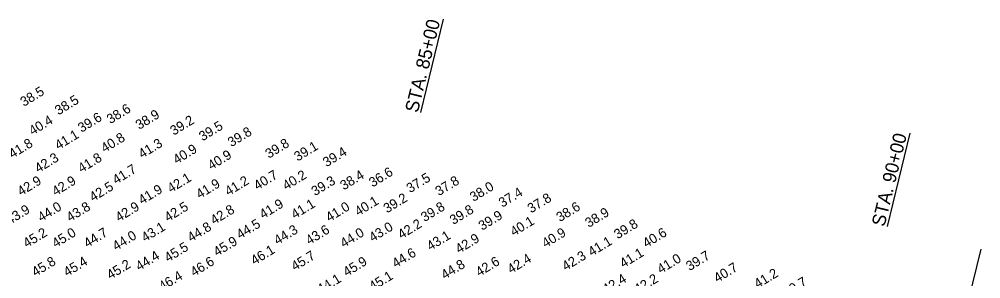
# Model space of a CAD drawing. Extents: x 409260 to 414340, y 1188556 to 1192902.
# Drawn here: x 412335 to 413336, y 1190993 to 1191263 of the extents above; entities that cross this region are included whole.
import ezdxf

# ---------------------------------------------------------------- set-up
doc = ezdxf.new("R2010")
doc.units = 0
for name, color, linetype in [('V-ALGN-TEXT', 7, 'Continuous'), ('V-ANNO-MATC', 7, 'Continuous'), ('V-TOPO-SOUN', 7, 'Continuous')]:
    doc.layers.add(name, color=color, linetype=linetype)

msp = doc.modelspace()

# ---------------------------------------------------------------- linework, layer by layer
at = {"layer": 'V-ALGN-TEXT'}
for p, q in [((412752.8, 1191165.8), (412776.5, 1191262.9)), ((413238.6, 1191047.3), (413262.3, 1191144.4))]:
    msp.add_line(p, q, dxfattribs=at)
at = {"layer": 'V-ANNO-MATC'}
msp.add_line((413335.8, 1191023.6), (413015.9, 1189712), dxfattribs=at)

# ---------------------------------------------------------------- texts
at = {"layer": 'V-ALGN-TEXT'}
for s, p in [('STA. 85+00', (412749.7, 1191164.8)), ('STA. 90+00', (413235.5, 1191046.3))]:
    msp.add_text(s, height=13.92, rotation=76.2946, dxfattribs=at).set_placement(p)
at = {"layer": 'V-TOPO-SOUN'}
for s, p in [('38.5 ', (412339.7, 1191171.6)), ('38.5 ', (412375.7, 1191162.7)), ('38.6 ', (412429.7, 1191153.6)), ('40.4 ', (412348.7, 1191141.6)), ('39.6 ', (412399.7, 1191144.6)), ('38.9 ', (412459.7, 1191147.6)), ('39.2 ', (412495.7, 1191141.6)), ('39.5 ', (412525.7, 1191135.7)), ('39.8 ', (412555.7, 1191129.6)), ('41.1 ', (412375.7, 1191126.6)), ('40.8 ', (412423.7, 1191123.6)), ('41.8 ', (412327.7, 1191117.6)), ('41.3 ', (412462.7, 1191117.6)), ('40.9 ', (412498.7, 1191111.6)), ('39.8 ', (412594.7, 1191117.6)), ('39.1 ', (412624.7, 1191114.6)), ('39.4 ', (412654.7, 1191108.7)), ('42.3 ', (412354.7, 1191102.6)), ('41.8 ', (412399.7, 1191102.6)), ('40.9 ', (412534.7, 1191105.6)), ('41.7 ', (412435.7, 1191090.6)), ('36.6 ', (412702.7, 1191087.7)), ('42.9 ', (412336.7, 1191078.6)), ('42.9 ', (412372.7, 1191078.6)), ('42.1 ', (412492.7, 1191081.7)), ('41.2 ', (412552.7, 1191078.6)), ('40.7 ', (412582.7, 1191084.6)), ('40.2 ', (412612.7, 1191084.6)), ('39.3 ', (412642.7, 1191078.6)), ('38.4 ', (412672.7, 1191084.6)), ('37.5 ', (412741.7, 1191081.7)), ('37.8 ', (412771.7, 1191078.6)), ('42.5 ', (412411.7, 1191072.6)), ('41.9 ', (412462.7, 1191069.6)), ('41.9 ', (412522.7, 1191075.6)), ('38.0 ', (412807.7, 1191072.6)), ('39.2 ', (412717.7, 1191060.7)), ('37.4 ', (412837.7, 1191066.6)), ('37.8 ', (412867.7, 1191060.7)), ('43.9 ', (412324.7, 1191048.6)), ('44.0 ', (412357.7, 1191051.6)), ('43.8 ', (412387.7, 1191051.6)), ('42.9 ', (412438.7, 1191051.6)), ('42.5 ', (412489.7, 1191051.6)), ('42.8 ', (412537.7, 1191048.6)), ('41.9 ', (412588.7, 1191054.6)), ('41.1 ', (412621.7, 1191054.6)), ('41.0 ', (412657.7, 1191051.6)), ('40.1 ', (412687.7, 1191057.6)), ('39.8 ', (412756.7, 1191051.6)), ('39.8 ', (412786.7, 1191048.6)), ('38.6 ', (412897.7, 1191051.6)), ('39.9 ', (412816.7, 1191042.6)), ('38.9 ', (412927.7, 1191045.6)), ('43.1 ', (412465.7, 1191030.6)), ('44.8 ', (412513.7, 1191030.6)), ('44.5 ', (412564.7, 1191033.7)), ('43.6 ', (412636.7, 1191027.6)), ('43.0 ', (412702.7, 1191030.6)), ('42.2 ', (412732.7, 1191033.7)), ('40.1 ', (412849.7, 1191036.6)), ('39.8 ', (412957.7, 1191033.7)), ('45.2 ', (412342.7, 1191024.6)), ('45.0 ', (412372.7, 1191024.6)), ('44.7 ', (412405.7, 1191024.6)), ('44.0 ', (412435.7, 1191021.6)), ('44.3 ', (412603.7, 1191027.6)), ('44.0 ', (412672.7, 1191024.6)), ('43.1 ', (412762.7, 1191021.6)), ('42.9 ', (412792.7, 1191018.6)), ('40.9 ', (412882.7, 1191024.6)), ('40.6 ', (412987.7, 1191024.6)), ('45.5 ', (412489.7, 1191009.6)), ('45.9 ', (412540.7, 1191015.6)), ('41.1 ', (412930.7, 1191015.6)), ('44.4 ', (412459.7, 1191000.6)), ('46.1 ', (412579.7, 1191006.7)), ('45.7 ', (412621.7, 1191000.6)), ('44.6 ', (412726.7, 1191003.6)), ('42.3 ', (412903.7, 1191000.6)), ('41.1 ', (412963.7, 1191003.6)), ('39.7 ', (413032.7, 1191000.6)), ('45.8 ', (412351.7, 1190994.6)), ('45.4 ', (412384.7, 1190994.6)), ('45.2 ', (412429.7, 1190991.6)), ('46.6 ', (412516.7, 1190994.6)), ('45.9 ', (412675.7, 1190994.6)), ('44.8 ', (412777.7, 1190991.6)), ('42.6 ', (412813.7, 1190994.6)), ('42.4 ', (412846.7, 1190997.6)), ('41.0 ', (413002.7, 1190997.6)), ('40.7 ', (413061.6, 1190988.3)), ('46.4 ', (412483.7, 1190979.6)), ('45.1 ', (412702.7, 1190979.6)), ('41.2 ', (413103.6, 1190982.3)), ('44.1 ', (412648.7, 1190976.6)), ('42.4 ', (412945.7, 1190976.6)), ('42.2 ', (412978.7, 1190976.6)), ('39.7 ', (413133.6, 1190973.3))]:
    msp.add_text(s, height=10, rotation=31.2939, dxfattribs=at).set_placement(p)

doc.saveas('drawing.dxf')
